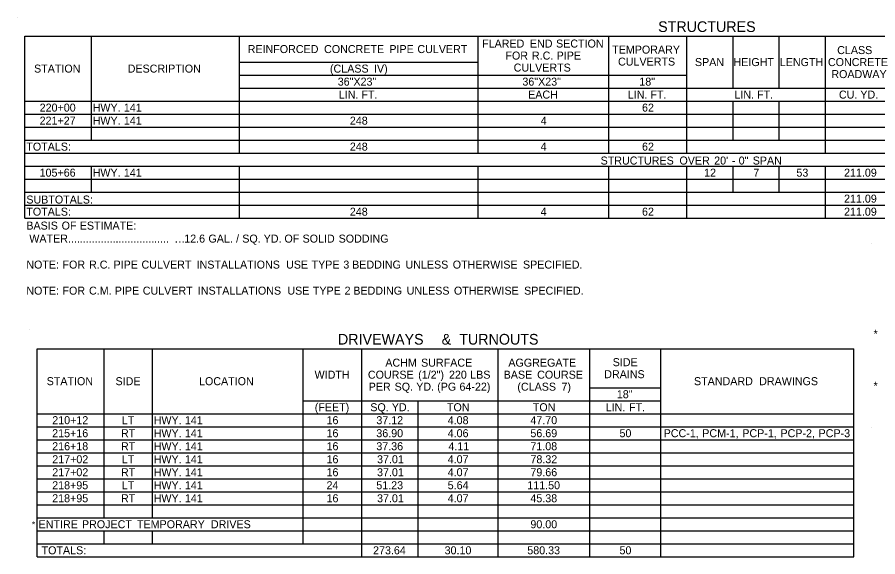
# Model space of a CAD drawing. Extents: x 1334738 to 1334853, y 402732 to 402753.
# Drawn here: x 1334821.7 to 1334837.83, y 402742.5 to 402752.61 of the extents above; entities that cross this region are included whole.
import ezdxf

# ---------------------------------------------------------------- set-up
doc = ezdxf.new("R2010")
doc.units = 0
doc.layers.add('Default', color=7, linetype='Continuous')

msp = doc.modelspace()

# ---------------------------------------------------------------- linework, layer by layer
at = {"layer": 'Default'}
for p, q in [((1334821.696, 402752.612), (1334821.696, 402752.612)), ((1334821.842, 402752.258), (1334846.839, 402752.258)), ((1334821.842, 402748.846), (1334821.842, 402752.258)), ((1334821.842, 402748.846), (1334821.842, 402752.258)), ((1334823.086, 402750.308), (1334823.086, 402752.258)), ((1334825.864, 402750.065), (1334825.864, 402752.258)), ((1334825.864, 402751.771), (1334825.864, 402752.258)), ((1334830.337, 402751.04), (1334830.337, 402752.258)), ((1334832.787, 402751.283), (1334832.787, 402752.258)), ((1334832.787, 402751.04), (1334832.787, 402752.258)), ((1334834.249, 402751.283), (1334834.249, 402752.258)), ((1334834.249, 402751.04), (1334834.249, 402752.258)), ((1334835.115, 402751.283), (1334835.115, 402752.258)), ((1334835.98, 402751.283), (1334835.98, 402752.258)), ((1334836.845, 402751.04), (1334836.845, 402752.258)), ((1334825.864, 402751.771), (1334830.337, 402751.771)), ((1334825.864, 402751.527), (1334834.249, 402751.527)), ((1334825.864, 402751.283), (1334832.787, 402751.283)), ((1334825.864, 402751.04), (1334825.864, 402751.283)), ((1334832.787, 402751.283), (1334842.823, 402751.283)), ((1334821.842, 402751.04), (1334846.839, 402751.04)), ((1334823.086, 402750.308), (1334823.086, 402751.04)), ((1334830.337, 402750.065), (1334830.337, 402751.04)), ((1334830.337, 402750.065), (1334830.337, 402751.04)), ((1334832.787, 402750.065), (1334832.787, 402751.04)), ((1334832.787, 402750.065), (1334832.787, 402751.04)), ((1334834.249, 402750.065), (1334834.249, 402751.04)), ((1334834.249, 402750.065), (1334834.249, 402751.04)), ((1334835.115, 402750.308), (1334835.115, 402751.04)), ((1334835.115, 402750.308), (1334835.115, 402751.04)), ((1334835.98, 402750.308), (1334835.98, 402751.04)), ((1334835.98, 402750.308), (1334835.98, 402751.04)), ((1334836.845, 402750.065), (1334836.845, 402751.04)), ((1334836.845, 402750.065), (1334836.845, 402751.04)), ((1334821.842, 402750.796), (1334846.839, 402750.796)), ((1334821.842, 402750.552), (1334846.839, 402750.552)), ((1334821.842, 402750.308), (1334846.839, 402750.308)), ((1334821.842, 402750.065), (1334846.839, 402750.065)), ((1334821.842, 402749.821), (1334846.839, 402749.821)), ((1334823.086, 402749.333), (1334823.086, 402749.821)), ((1334823.086, 402749.333), (1334823.086, 402749.821)), ((1334825.864, 402748.846), (1334825.864, 402749.821)), ((1334830.337, 402748.846), (1334830.337, 402749.821)), ((1334830.337, 402748.846), (1334830.337, 402749.821)), ((1334832.787, 402748.846), (1334832.787, 402749.821)), ((1334832.787, 402748.846), (1334832.787, 402749.821)), ((1334834.249, 402748.846), (1334834.249, 402749.821)), ((1334834.249, 402748.846), (1334834.249, 402749.821)), ((1334835.115, 402749.333), (1334835.115, 402749.821)), ((1334835.115, 402749.333), (1334835.115, 402749.821)), ((1334835.98, 402749.333), (1334835.98, 402749.821)), ((1334835.98, 402749.333), (1334835.98, 402749.821)), ((1334836.845, 402748.846), (1334836.845, 402749.821)), ((1334836.845, 402748.846), (1334836.845, 402749.821)), ((1334821.842, 402749.577), (1334846.839, 402749.577)), ((1334821.842, 402749.333), (1334846.839, 402749.333)), ((1334823.086, 402749.333), (1334825.864, 402749.333)), ((1334825.864, 402749.333), (1334841.903, 402749.333)), ((1334821.842, 402749.09), (1334846.839, 402749.09)), ((1334825.864, 402748.846), (1334825.864, 402749.09)), ((1334821.842, 402748.846), (1334846.839, 402748.846)), ((1334837.7, 402748.379), (1334837.7, 402748.379)), ((1334821.926, 402746.754), (1334821.926, 402746.754)), ((1334822.072, 402746.4), (1334837.38, 402746.4)), ((1334822.072, 402742.5), (1334822.072, 402746.4)), ((1334822.072, 402742.5), (1334822.072, 402746.4)), ((1334823.328, 402743.232), (1334823.328, 402746.4)), ((1334823.328, 402743.232), (1334823.328, 402746.4)), ((1334824.23, 402743.232), (1334824.23, 402746.4)), ((1334824.23, 402743.232), (1334824.23, 402746.4)), ((1334827.057, 402742.744), (1334827.057, 402746.4)), ((1334828.154, 402742.5), (1334828.154, 402746.4)), ((1334828.154, 402742.5), (1334828.154, 402746.4)), ((1334830.713, 402742.5), (1334830.713, 402746.4)), ((1334830.713, 402742.5), (1334830.713, 402746.4)), ((1334832.432, 402742.5), (1334832.432, 402746.4)), ((1334833.76, 402742.5), (1334833.76, 402746.4)), ((1334833.76, 402743.475), (1334833.76, 402746.4)), ((1334837.38, 402742.5), (1334837.38, 402746.4)), ((1334832.432, 402745.669), (1334833.76, 402745.669)), ((1334827.057, 402745.425), (1334833.76, 402745.425)), ((1334827.057, 402742.744), (1334827.057, 402745.425)), ((1334829.214, 402742.5), (1334829.214, 402745.425)), ((1334829.214, 402742.5), (1334829.214, 402745.425)), ((1334832.432, 402743.475), (1334832.432, 402745.425)), ((1334822.072, 402745.182), (1334837.38, 402745.182)), ((1334833.76, 402745.182), (1334837.38, 402745.182)), ((1334822.072, 402744.938), (1334837.38, 402744.938)), ((1334837.7, 402744.927), (1334837.7, 402744.927)), ((1334822.072, 402744.694), (1334837.38, 402744.694)), ((1334822.072, 402744.45), (1334837.38, 402744.45)), ((1334822.072, 402744.207), (1334837.38, 402744.207)), ((1334822.072, 402743.963), (1334837.38, 402743.963)), ((1334822.072, 402743.719), (1334837.38, 402743.719)), ((1334822.072, 402743.475), (1334837.38, 402743.475)), ((1334822.072, 402743.232), (1334837.38, 402743.232)), ((1334832.432, 402743.232), (1334833.76, 402743.232)), ((1334832.432, 402742.5), (1334832.432, 402743.232)), ((1334833.76, 402743.232), (1334837.38, 402743.232)), ((1334833.76, 402742.5), (1334833.76, 402743.232)), ((1334822.072, 402742.988), (1334837.38, 402742.988)), ((1334823.328, 402742.744), (1334823.328, 402742.988)), ((1334823.328, 402742.744), (1334823.328, 402742.988)), ((1334824.23, 402742.744), (1334824.23, 402742.988)), ((1334824.23, 402742.744), (1334824.23, 402742.988)), ((1334833.76, 402742.988), (1334837.38, 402742.988)), ((1334822.072, 402742.744), (1334837.38, 402742.744)), ((1334822.072, 402742.744), (1334837.38, 402742.744)), ((1334822.072, 402742.5), (1334837.38, 402742.5))]:
    msp.add_line(p, q, dxfattribs=at)

# ---------------------------------------------------------------- texts
for s, height, p in [('STRUCTURES', 0.2, (1334833.709, 402752.335)), ('FLARED', 0.15, (1334830.41, 402752.043)), (' END', 0.15, (1334831.25, 402752.043)), (' SECTION', 0.15, (1334831.74, 402752.043)), ('REINFORCED', 0.15, (1334826.016, 402751.94)), (' CONCRETE', 0.15, (1334827.392, 402751.94)), (' PIPE', 0.15, (1334828.616, 402751.94)), (' CULVERT', 0.15, (1334829.141, 402751.94)), ('TEMPORARY', 0.15, (1334832.848, 402751.93)), ('CLASS', 0.15, (1334837.065, 402751.921)), ('FOR', 0.15, (1334830.847, 402751.818)), (' R.C.', 0.15, (1334831.288, 402751.818)), (' PIPE', 0.15, (1334831.751, 402751.818)), ('CULVERTS', 0.15, (1334832.958, 402751.705)), ('SPAN', 0.15, (1334834.399, 402751.696)), ('HEIGHT ', 0.15, (1334835.122, 402751.696)), ('LENGTH', 0.15, (1334835.99, 402751.696)), ('CONCRETE', 0.15, (1334836.892, 402751.696)), ('STATION', 0.15, (1334822.012, 402751.574)), ('DESCRIPTION', 0.15, (1334823.767, 402751.574)), ('(CLASS', 0.15, (1334827.558, 402751.574)), (' IV)', 0.15, (1334828.328, 402751.574)), ('CULVERTS', 0.15, (1334831.002, 402751.593)), ('ROADWAY', 0.15, (1334836.956, 402751.471)), ('36"X23"', 0.15, (1334827.704, 402751.33)), ('36"X23"', 0.15, (1334831.165, 402751.33)), ('18"', 0.15, (1334833.357, 402751.33)), ('LIN. FT.', 0.15, (1334827.724, 402751.087)), ('EACH', 0.15, (1334831.273, 402751.087)), ('LIN. FT.', 0.15, (1334833.141, 402751.087)), ('LIN. FT.', 0.15, (1334835.139, 402751.087)), ('CU. YD.', 0.15, (1334837.098, 402751.087)), ('220+00', 0.15, (1334822.117, 402750.843)), ('HWY.', 0.15, (1334823.11, 402750.843)), (' 141', 0.15, (1334823.639, 402750.843)), ('62', 0.15, (1334833.407, 402750.843)), ('221+27', 0.15, (1334822.116, 402750.599)), ('HWY.', 0.15, (1334823.11, 402750.599)), (' 141', 0.15, (1334823.639, 402750.599)), ('248', 0.15, (1334827.931, 402750.599)), ('4', 0.15, (1334831.509, 402750.599)), ('TOTALS:', 0.15, (1334821.867, 402750.112)), ('248', 0.15, (1334827.931, 402750.112)), ('4', 0.15, (1334831.506, 402750.112)), ('62', 0.15, (1334833.407, 402750.112)), ('STRUCTURES', 0.15, (1334832.631, 402749.851)), (' OVER', 0.15, (1334834.053, 402749.851)), (" 20'", 0.15, (1334834.704, 402749.851)), (' -', 0.15, (1334835.036, 402749.851)), (' 0"', 0.15, (1334835.163, 402749.851)), (' SPAN', 0.15, (1334835.426, 402749.851)), ('105+66', 0.15, (1334822.116, 402749.624)), ('HWY.', 0.15, (1334823.11, 402749.624)), (' 141', 0.15, (1334823.639, 402749.624)), ('12', 0.15, (1334834.571, 402749.624)), ('7', 0.15, (1334835.494, 402749.624)), ('53', 0.15, (1334836.301, 402749.624)), ('211.09', 0.15, (1334837.194, 402749.624)), ('SUBTOTALS:', 0.15, (1334821.867, 402749.12)), ('211.09', 0.15, (1334837.194, 402749.137)), ('TOTALS:', 0.15, (1334821.867, 402748.893)), ('248', 0.15, (1334827.931, 402748.893)), ('4', 0.15, (1334831.506, 402748.893)), ('62', 0.15, (1334833.407, 402748.893)), ('211.09', 0.15, (1334837.194, 402748.893)), ('BASIS', 0.15, (1334821.867, 402748.632)), (' OF', 0.15, (1334822.473, 402748.632)), (' ESTIMATE:', 0.15, (1334822.813, 402748.632)), (' WATER..................................', 0.15, (1334821.867, 402748.388)), ('12.6', 0.15, (1334824.827, 402748.388)), (' GAL.', 0.15, (1334825.225, 402748.388)), (' /', 0.15, (1334825.743, 402748.388)), (' SQ.', 0.15, (1334825.859, 402748.388)), (' YD.', 0.15, (1334826.26, 402748.388)), (' OF', 0.15, (1334826.649, 402748.388)), (' SOLID', 0.15, (1334826.989, 402748.388)), (' SODDING', 0.15, (1334827.665, 402748.388)), ('…', 0.15, (1334824.642, 402748.388)), ('NOTE:', 0.15, (1334821.867, 402747.901)), (' FOR', 0.15, (1334822.489, 402747.901)), (' R.C.', 0.15, (1334822.987, 402747.901)), (' PIPE', 0.15, (1334823.446, 402747.901)), (' CULVERT', 0.15, (1334823.97, 402747.901)), (' INSTALLATIONS', 0.15, (1334825.003, 402747.901)), (' USE', 0.15, (1334826.68, 402747.901)), (' TYPE', 0.15, (1334827.158, 402747.901)), (' 3', 0.15, (1334827.753, 402747.901)), (' BEDDING', 0.15, (1334827.918, 402747.901)), (' UNLESS', 0.15, (1334828.918, 402747.901)), (' OTHERWISE', 0.15, (1334829.804, 402747.901)), (' SPECIFIED.', 0.15, (1334831.12, 402747.901)), ('NOTE:', 0.15, (1334821.867, 402747.413)), (' FOR', 0.15, (1334822.489, 402747.413)), (' C.M.', 0.15, (1334822.987, 402747.413)), (' PIPE', 0.15, (1334823.469, 402747.413)), (' CULVERT', 0.15, (1334823.994, 402747.413)), (' INSTALLATIONS', 0.15, (1334825.026, 402747.413)), (' USE', 0.15, (1334826.704, 402747.413)), (' TYPE', 0.15, (1334827.182, 402747.413)), (' 2', 0.15, (1334827.776, 402747.413)), (' BEDDING', 0.15, (1334827.94, 402747.413)), (' UNLESS', 0.15, (1334828.94, 402747.413)), (' OTHERWISE', 0.15, (1334829.826, 402747.413)), (' SPECIFIED.', 0.15, (1334831.142, 402747.413)), ('DRIVEWAYS', 0.2, (1334827.708, 402746.477)), (' &', 0.2, (1334829.577, 402746.477)), (' TURNOUTS', 0.2, (1334829.907, 402746.477)), ('*', 0.15, (1334837.747, 402746.605)), ('ACHM', 0.15, (1334828.596, 402746.063)), (' SURFACE', 0.15, (1334829.21, 402746.063)), ('AGGREGATE', 0.15, (1334830.902, 402746.063)), ('SIDE', 0.15, (1334832.857, 402746.072)), ('STATION', 0.15, (1334822.248, 402745.716)), ('SIDE', 0.15, (1334823.539, 402745.716)), ('LOCATION', 0.15, (1334825.104, 402745.716)), ('WIDTH', 0.15, (1334827.27, 402745.838)), ('COURSE', 0.15, (1334828.269, 402745.838)), (' (1/2")', 0.15, (1334829.156, 402745.838)), (' 220', 0.15, (1334829.733, 402745.838)), (' LBS', 0.15, (1334830.131, 402745.838)), ('BASE', 0.15, (1334830.814, 402745.838)), (' COURSE', 0.15, (1334831.386, 402745.838)), ('DRAINS', 0.15, (1334832.699, 402745.847)), ('STANDARD', 0.15, (1334834.381, 402745.716)), (' DRAWINGS', 0.15, (1334835.547, 402745.716)), ('PER', 0.15, (1334828.284, 402745.613)), (' SQ.', 0.15, (1334828.714, 402745.613)), (' YD.', 0.15, (1334829.119, 402745.613)), (' (PG', 0.15, (1334829.512, 402745.613)), (' 64-22)', 0.15, (1334829.93, 402745.613)), ('(CLASS', 0.15, (1334831.071, 402745.613)), (' 7)', 0.15, (1334831.841, 402745.613)), ('*', 0.15, (1334837.747, 402745.63)), ('18"', 0.15, (1334832.935, 402745.472)), ('(FEET)', 0.15, (1334827.273, 402745.228)), ('SQ.', 0.15, (1334828.314, 402745.228)), (' YD.', 0.15, (1334828.661, 402745.228)), ('TON', 0.15, (1334829.751, 402745.228)), ('TON', 0.15, (1334831.36, 402745.228)), ('LIN.', 0.15, (1334832.726, 402745.228)), (' FT.', 0.15, (1334833.108, 402745.228)), ('210+12', 0.15, (1334822.353, 402744.985)), ('LT', 0.15, (1334823.658, 402744.985)), ('HWY.', 0.15, (1334824.254, 402744.985)), (' 141', 0.15, (1334824.783, 402744.985)), ('16', 0.15, (1334827.494, 402744.985)), ('37.12', 0.15, (1334828.428, 402744.985)), ('4.08', 0.15, (1334829.765, 402744.985)), ('47.70', 0.15, (1334831.315, 402744.985)), ('215+16', 0.15, (1334822.352, 402744.741)), ('RT', 0.15, (1334823.641, 402744.741)), ('HWY.', 0.15, (1334824.254, 402744.741)), (' 141', 0.15, (1334824.783, 402744.741)), ('16', 0.15, (1334827.494, 402744.741)), ('36.90', 0.15, (1334828.427, 402744.741)), ('4.06', 0.15, (1334829.765, 402744.741)), ('56.69', 0.15, (1334831.315, 402744.741)), ('50', 0.15, (1334832.985, 402744.741)), ('PCC-1,', 0.15, (1334833.813, 402744.741)), (' PCM-1,', 0.15, (1334834.481, 402744.741)), (' PCP-1,', 0.15, (1334835.231, 402744.741)), (' PCP-2,', 0.15, (1334835.946, 402744.741)), (' PCP-3', 0.15, (1334836.661, 402744.741)), ('216+18', 0.15, (1334822.352, 402744.497)), ('RT', 0.15, (1334823.641, 402744.497)), ('HWY.', 0.15, (1334824.254, 402744.497)), (' 141', 0.15, (1334824.783, 402744.497)), ('16', 0.15, (1334827.494, 402744.497)), ('37.36', 0.15, (1334828.427, 402744.497)), ('4.11', 0.15, (1334829.779, 402744.497)), ('71.08', 0.15, (1334831.315, 402744.497)), ('217+02', 0.15, (1334822.353, 402744.253)), ('LT', 0.15, (1334823.658, 402744.253)), ('HWY.', 0.15, (1334824.254, 402744.253)), (' 141', 0.15, (1334824.783, 402744.253)), ('16', 0.15, (1334827.494, 402744.253)), ('37.01', 0.15, (1334828.441, 402744.253)), ('4.07', 0.15, (1334829.765, 402744.253)), ('78.32', 0.15, (1334831.316, 402744.253)), ('217+02', 0.15, (1334822.353, 402744.01)), ('RT', 0.15, (1334823.641, 402744.01)), ('HWY.', 0.15, (1334824.254, 402744.01)), (' 141', 0.15, (1334824.783, 402744.01)), ('16', 0.15, (1334827.494, 402744.01)), ('37.01', 0.15, (1334828.441, 402744.01)), ('4.07', 0.15, (1334829.765, 402744.01)), ('79.66', 0.15, (1334831.315, 402744.01)), ('218+95', 0.15, (1334822.352, 402743.766)), ('LT', 0.15, (1334823.658, 402743.766)), ('HWY.', 0.15, (1334824.254, 402743.766)), (' 141', 0.15, (1334824.783, 402743.766)), ('24', 0.15, (1334827.494, 402743.766)), ('51.23', 0.15, (1334828.427, 402743.766)), ('5.64', 0.15, (1334829.765, 402743.766)), ('111.50', 0.15, (1334831.257, 402743.766)), ('218+95', 0.15, (1334822.352, 402743.522)), ('RT', 0.15, (1334823.641, 402743.522)), ('HWY.', 0.15, (1334824.254, 402743.522)), (' 141', 0.15, (1334824.783, 402743.522)), ('16', 0.15, (1334827.494, 402743.522)), ('37.01', 0.15, (1334828.441, 402743.522)), ('4.07', 0.15, (1334829.765, 402743.522)), ('45.38', 0.15, (1334831.315, 402743.522)), ('*', 0.125, (1334821.968, 402743.047)), ('ENTIRE', 0.15, (1334822.097, 402743.035)), (' PROJECT', 0.15, (1334822.854, 402743.035)), (' TEMPORARY', 0.15, (1334823.886, 402743.035)), (' DRIVES', 0.15, (1334825.271, 402743.035)), ('90.00', 0.15, (1334831.315, 402743.035)), (' TOTALS:', 0.15, (1334822.097, 402742.547)), ('273.64', 0.15, (1334828.366, 402742.547)), ('30.10', 0.15, (1334829.707, 402742.547)), ('580.33', 0.15, (1334831.257, 402742.547)), ('50', 0.15, (1334832.985, 402742.547))]:
    msp.add_text(s, height=height, dxfattribs=at).set_placement(p)

doc.saveas('drawing.dxf')
